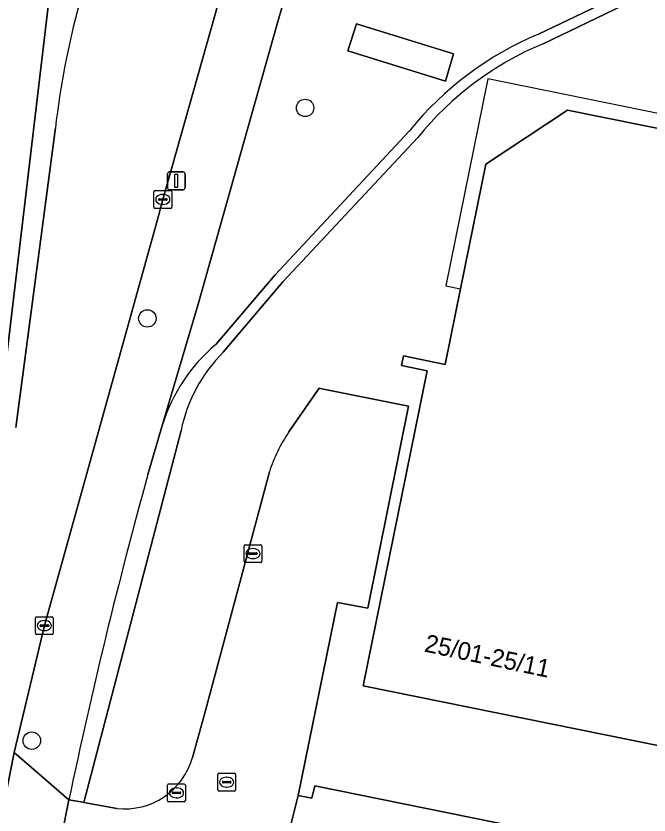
# Model space of a CAD drawing. Extents: x 157692 to 159674, y 381452 to 383291.
# Drawn here: x 158509.71 to 158545.26, y 382034.2 to 382079.09 of the extents above; entities that cross this region are included whole.
import ezdxf

# ---------------------------------------------------------------- set-up
doc = ezdxf.new("R2010")
doc.units = 0
for name, color, linetype in [('IMGEO_Boom', 7, 'Continuous'), ('IMGEO_Erf', 7, 'Continuous'), ('IMGEO_Groenvoorziening', 7, 'Continuous'), ('IMGEO_Haag', 7, 'Continuous'), ('IMGEO_Kolk', 7, 'Continuous'), ('IMGEO_Lichtmast', 7, 'Continuous'), ('IMGEO_Pand', 7, 'Continuous'), ('IMGEO_Pand_nummerreeks', 7, 'Continuous'), ('IMGEO_Pand_overbouw', 7, 'Continuous'), ('IMGEO_Rijbaan_lokaal_gesloten', 7, 'Continuous'), ('IMGEO_Rijbaan_lokaal_open', 7, 'Continuous'), ('IMGEO_Rioolput', 7, 'Continuous'), ('IMGEO_Verkeerseiland_groen', 7, 'Continuous'), ('IMGEO_Voetpad_gesloten', 7, 'Continuous'), ('IMGEO_Voetpad_open', 7, 'Continuous')]:
    doc.layers.add(name, color=color, linetype=linetype)

msp = doc.modelspace()

# ---------------------------------------------------------------- linework, layer by layer
at = {"layer": 'IMGEO_Boom'}
for centre in [(158525.946, 382073.928), (158517.084, 382062.098), (158510.594, 382038.377)]:
    msp.add_circle(centre, 0.489, dxfattribs=at)
at = {"layer": 'IMGEO_Erf'}
for points in [[(158549.351, 382081.923), (158544.304, 382079.926), (158539.307, 382077.53)], [(158545.753, 382038.099), (158529.205, 382041.46), (158532.366, 382057.038), (158532.796, 382059.159), (158531.366, 382059.452), (158531.476, 382059.991), (158533.808, 382059.514), (158534.67, 382063.763), (158536.091, 382070.76), (158540.685, 382073.808), (158551.628, 382071.582)], [(158532.278, 382072.266), (158524.702, 382064.158), (158521.35, 382060.207)], [(158525.034, 382055.722), (158526.735, 382058.178), (158526.89, 382058.147), (158531.761, 382057.161), (158529.467, 382045.826), (158527.765, 382046.147), (158525.552, 382035.293), (158526.323, 382035.147), (158526.484, 382035.842), (158558.034, 382029.439), (158559.163, 382029.191)], [(158518.976, 382055.81), (158513.524, 382034.906), (158515.374, 382034.573)], [(158519.613, 382037.428), (158520.266, 382039.789), (158523.937, 382053.475)]]:
    msp.add_lwpolyline(points, dxfattribs=at)
for centre, radius, start, end in [((158546.234, 382060.956), 17.963, 112.681, 140.9779), ((158527.558, 382054.016), 8.767, 135.0777, 168.1919), ((158532.278, 382050.794), 8.761, 145.7735, 162.1826), ((158515.818, 382038.488), 3.94, 263.5322, 344.3889)]:
    msp.add_arc(centre, radius, start, end, dxfattribs=at)
at = {"layer": 'IMGEO_Groenvoorziening'}
for points in [[(158532.785, 382090.725), (158530.685, 382089.566), (158531.088, 382089.437), (158530.655, 382088.082), (158529.462, 382088.463), (158529.505, 382088.595), (158526.701, 382085.7), (158526.634, 382085.603), (158526.156, 382084.918), (158525.864, 382083.985), (158524.781, 382080.019), (158524.718, 382079.809), (158524.35, 382078.573), (158519.936, 382062.893), (158517.941, 382056.136)], [(158539.307, 382077.53), (158544.304, 382079.926), (158549.351, 382081.923), (158553.579, 382082.999), (158557.322, 382083.532), (158561.047, 382084.02), (158565.823, 382083.768), (158570.839, 382083.106), (158574.936, 382082.265), (158656.531, 382065.514), (158658.251, 382065.165), (158658.369, 382065.753), (158656.651, 382066.102), (158575.057, 382082.853), (158570.941, 382083.698), (158565.878, 382084.366), (158561.024, 382084.622), (158557.24, 382084.126), (158553.463, 382083.589), (158549.165, 382082.495), (158544.064, 382080.476), (158539.061, 382078.078)], [(158539.061, 382078.078), (158544.064, 382080.476), (158549.165, 382082.495)], [(158520.926, 382060.631), (158524.254, 382064.558), (158531.812, 382072.644)], [(158531.812, 382072.644), (158524.254, 382064.558), (158520.926, 382060.631)], [(158521.35, 382060.207), (158524.702, 382064.158), (158532.278, 382072.266)], [(158517.941, 382056.136), (158517.115, 382053.336)], [(158512.682, 382035.058), (158513.351, 382034.937), (158513.524, 382034.906), (158518.976, 382055.81)]]:
    msp.add_lwpolyline(points, dxfattribs=at)
msp.add_lwpolyline([(158534.274, 382076.969), (158533.821, 382075.438), (158528.352, 382077.128), (158528.826, 382078.647)], close=True, dxfattribs=at)
for centre, radius, start, end in [((158546.239, 382060.95), 18.572, 112.7386, 140.9734), ((158546.239, 382060.95), 18.572, 112.7386, 140.9734), ((158546.234, 382060.956), 17.963, 112.681, 140.9779), ((158527.111, 382053.285), 9.603, 130.0967, 162.7294), ((158527.111, 382053.285), 9.603, 130.0967, 162.7294), ((158527.558, 382054.016), 8.767, 135.0777, 168.1919), ((158799.672, 381975.13), 293.18, 164.52906, 168.20529)]:
    msp.add_arc(centre, radius, start, end, dxfattribs=at)
at = {"layer": 'IMGEO_Haag'}
for points in [[(158539.307, 382077.53), (158544.304, 382079.926), (158549.351, 382081.923), (158553.579, 382082.999), (158557.322, 382083.532), (158561.047, 382084.02), (158565.823, 382083.768), (158570.839, 382083.106), (158574.936, 382082.265), (158656.531, 382065.514), (158658.251, 382065.165), (158658.369, 382065.753), (158656.651, 382066.102), (158575.057, 382082.853), (158570.941, 382083.698), (158565.878, 382084.366), (158561.024, 382084.622), (158557.24, 382084.126), (158553.463, 382083.589), (158549.165, 382082.495), (158544.064, 382080.476), (158539.061, 382078.078)], [(158531.812, 382072.644), (158524.254, 382064.558), (158520.926, 382060.631)], [(158521.35, 382060.207), (158524.702, 382064.158), (158532.278, 382072.266)], [(158517.941, 382056.136), (158517.115, 382053.336)], [(158512.682, 382035.058), (158513.351, 382034.937), (158513.524, 382034.906), (158518.976, 382055.81)]]:
    msp.add_lwpolyline(points, dxfattribs=at)
for centre, radius, start, end in [((158546.239, 382060.95), 18.572, 112.7386, 140.9734), ((158546.234, 382060.956), 17.963, 112.681, 140.9779), ((158527.111, 382053.285), 9.603, 130.0967, 162.7294), ((158527.558, 382054.016), 8.767, 135.0777, 168.1919), ((158799.672, 381975.13), 293.18, 164.52906, 168.20529)]:
    msp.add_arc(centre, radius, start, end, dxfattribs=at)
at = {"layer": 'IMGEO_Kolk'}
for p, q in [((158517.527, 382069.284), (158518.379, 382069.284)), ((158517.452, 382068.358), (158517.452, 382069.21)), ((158517.94, 382069.064), (158517.965, 382069.064)), ((158518.453, 382069.21), (158518.453, 382068.358)), ((158517.711, 382068.778), (158517.711, 382068.79)), ((158518.149, 382068.741), (158517.751, 382068.741)), ((158517.754, 382068.827), (158518.152, 382068.827)), ((158517.963, 382068.504), (158517.938, 382068.504)), ((158518.195, 382068.79), (158518.195, 382068.778)), ((158518.379, 382068.284), (158517.527, 382068.284)), ((158522.515, 382048.459), (158522.515, 382049.311)), ((158522.59, 382049.385), (158523.442, 382049.385)), ((158523.003, 382049.165), (158523.028, 382049.165)), ((158523.516, 382049.311), (158523.516, 382048.459)), ((158522.774, 382048.879), (158522.774, 382048.891)), ((158523.212, 382048.842), (158522.814, 382048.842)), ((158522.817, 382048.928), (158523.215, 382048.928)), ((158523.258, 382048.891), (158523.258, 382048.879)), ((158523.442, 382048.385), (158522.59, 382048.385)), ((158523.026, 382048.605), (158523.001, 382048.605)), ((158510.799, 382044.415), (158510.799, 382045.267)), ((158510.874, 382045.341), (158511.726, 382045.341)), ((158511.287, 382045.121), (158511.312, 382045.121)), ((158511.8, 382045.267), (158511.8, 382044.415)), ((158511.058, 382044.835), (158511.058, 382044.847)), ((158511.496, 382044.798), (158511.098, 382044.798)), ((158511.101, 382044.884), (158511.499, 382044.884)), ((158511.542, 382044.847), (158511.542, 382044.835)), ((158511.726, 382044.341), (158510.874, 382044.341)), ((158511.31, 382044.561), (158511.285, 382044.561)), ((158518.219, 382035.019), (158518.219, 382035.871)), ((158518.294, 382035.945), (158519.146, 382035.945)), ((158518.707, 382035.725), (158518.732, 382035.725)), ((158519.22, 382035.871), (158519.22, 382035.019)), ((158518.478, 382035.439), (158518.478, 382035.451)), ((158518.916, 382035.402), (158518.518, 382035.402)), ((158518.521, 382035.488), (158518.919, 382035.488)), ((158518.73, 382035.165), (158518.705, 382035.165)), ((158518.962, 382035.451), (158518.962, 382035.439)), ((158519.146, 382034.945), (158518.294, 382034.945))]:
    msp.add_line(p, q, dxfattribs=at)
for points in [[(158517.527, 382069.284), (158518.379, 382069.284)], [(158517.452, 382068.358), (158517.452, 382069.21)], [(158518.453, 382069.21), (158518.453, 382068.358)], [(158518.379, 382068.284), (158517.527, 382068.284)], [(158522.515, 382048.459), (158522.515, 382049.311)], [(158522.59, 382049.385), (158523.442, 382049.385)], [(158523.516, 382049.311), (158523.516, 382048.459)], [(158523.442, 382048.385), (158522.59, 382048.385)], [(158510.799, 382044.415), (158510.799, 382045.267)], [(158510.874, 382045.341), (158511.726, 382045.341)], [(158511.8, 382045.267), (158511.8, 382044.415)], [(158511.726, 382044.341), (158510.874, 382044.341)], [(158518.219, 382035.019), (158518.219, 382035.871)], [(158518.294, 382035.945), (158519.146, 382035.945)], [(158519.22, 382035.871), (158519.22, 382035.019)], [(158519.146, 382034.945), (158518.294, 382034.945)]]:
    msp.add_lwpolyline(points, dxfattribs=at)
for centre, radius, start, end in [((158517.529, 382069.208), 0.0765, 91.552, 178.448), ((158517.529, 382069.208), 0.0765, 91.552, 178.448), ((158518.377, 382069.208), 0.0765, 1.552, 88.448), ((158518.377, 382069.208), 0.0765, 1.552, 88.448), ((158517.751, 382068.787), 0.0403, 85.8775, 175.7526), ((158517.748, 382068.777), 0.0366, 178.938, 274.7102), ((158518.152, 382068.784), 0.043, 264.8664, 352.4533), ((158518.156, 382068.789), 0.0386, 1.7309, 96.639), ((158517.529, 382068.36), 0.0765, 181.552, 268.448), ((158517.529, 382068.36), 0.0765, 181.552, 268.448), ((158518.377, 382068.36), 0.0765, 271.552, 358.448), ((158518.377, 382068.36), 0.0765, 271.552, 358.448), ((158522.592, 382049.309), 0.0765, 91.552, 178.448), ((158522.592, 382049.309), 0.0765, 91.552, 178.448), ((158523.44, 382049.309), 0.0765, 1.552, 88.448), ((158523.44, 382049.309), 0.0765, 1.552, 88.448), ((158522.814, 382048.888), 0.0403, 85.8775, 175.7526), ((158522.811, 382048.878), 0.0366, 178.938, 274.7102), ((158523.215, 382048.885), 0.043, 264.8664, 352.4533), ((158523.219, 382048.89), 0.0386, 1.7309, 96.639), ((158522.592, 382048.461), 0.0765, 181.552, 268.448), ((158522.592, 382048.461), 0.0765, 181.552, 268.448), ((158523.44, 382048.461), 0.0765, 271.552, 358.448), ((158523.44, 382048.461), 0.0765, 271.552, 358.448), ((158510.876, 382045.265), 0.0765, 91.552, 178.448), ((158510.876, 382045.265), 0.0765, 91.552, 178.448), ((158511.724, 382045.265), 0.0765, 1.552, 88.448), ((158511.724, 382045.265), 0.0765, 1.552, 88.448), ((158511.098, 382044.844), 0.0403, 85.8775, 175.7526), ((158511.095, 382044.834), 0.0366, 178.938, 274.7102), ((158511.499, 382044.841), 0.043, 264.8664, 352.4533), ((158511.503, 382044.846), 0.0386, 1.7309, 96.639), ((158510.876, 382044.417), 0.0765, 181.552, 268.448), ((158510.876, 382044.417), 0.0765, 181.552, 268.448), ((158511.724, 382044.417), 0.0765, 271.552, 358.448), ((158511.724, 382044.417), 0.0765, 271.552, 358.448), ((158518.296, 382035.869), 0.0765, 91.552, 178.448), ((158518.296, 382035.869), 0.0765, 91.552, 178.448), ((158519.144, 382035.869), 0.0765, 1.552, 88.448), ((158519.144, 382035.869), 0.0765, 1.552, 88.448), ((158518.518, 382035.448), 0.0403, 85.8775, 175.7526), ((158518.515, 382035.438), 0.0366, 178.938, 274.7102), ((158518.919, 382035.445), 0.043, 264.8664, 352.4533), ((158518.923, 382035.45), 0.0386, 1.7309, 96.639), ((158518.296, 382035.021), 0.0765, 181.552, 268.448), ((158518.296, 382035.021), 0.0765, 181.552, 268.448), ((158519.144, 382035.021), 0.0765, 271.552, 358.448), ((158519.144, 382035.021), 0.0765, 271.552, 358.448)]:
    msp.add_arc(centre, radius, start, end, dxfattribs=at)
for centre, major_axis, ratio, start_param, end_param in [((158517.939, 382068.784), (-0.387, 0.002), 0.722429, 4.712389, 7.853982), ((158517.964, 382068.784), (-0.39, 0.002), 0.717154, 1.570796, 4.712389), ((158523.002, 382048.885), (-0.387, 0.002), 0.722429, 4.712389, 7.853982), ((158523.027, 382048.885), (-0.39, 0.002), 0.717154, 1.570796, 4.712389), ((158511.286, 382044.841), (-0.387, 0.002), 0.722429, 4.712389, 7.853982), ((158511.311, 382044.841), (-0.39, 0.002), 0.717154, 1.570796, 4.712389), ((158518.706, 382035.445), (-0.387, 0.002), 0.722429, 4.712389, 7.853982), ((158518.731, 382035.445), (-0.39, 0.002), 0.717154, 1.570796, 4.712389)]:
    msp.add_ellipse(centre, major_axis=major_axis, ratio=ratio, start_param=start_param, end_param=end_param, dxfattribs=at)
at = {"layer": 'IMGEO_Lichtmast'}
for p, q in [((158518.214, 382069.429), (158518.214, 382070.229)), ((158518.214, 382070.229), (158518.214, 382069.429)), ((158518.314, 382070.329), (158519.104, 382070.329)), ((158519.104, 382070.329), (158518.314, 382070.329)), ((158519.204, 382070.229), (158519.204, 382069.429)), ((158519.204, 382069.429), (158519.204, 382070.229)), ((158519.104, 382069.329), (158518.314, 382069.329)), ((158518.314, 382069.329), (158519.104, 382069.329))]:
    msp.add_line(p, q, dxfattribs=at)
msp.add_lwpolyline([(158518.634, 382070.204), (158518.784, 382070.204), (158518.784, 382069.454), (158518.634, 382069.454), (158518.634, 382070.204)], dxfattribs=at)
for centre, start, end in [((158518.314, 382070.229), 90, 180), ((158518.314, 382070.229), 90, 180), ((158519.104, 382070.229), 0, 90), ((158519.104, 382070.229), 360, 90), ((158518.314, 382069.429), 180, 270), ((158518.314, 382069.429), 180, 270), ((158519.104, 382069.429), 270, 0), ((158519.104, 382069.429), 270, 0)]:
    msp.add_arc(centre, 0.1, start, end, dxfattribs=at)
at = {"layer": 'IMGEO_Pand'}
msp.add_lwpolyline([(158551.628, 382071.582), (158540.685, 382073.808), (158536.091, 382070.76), (158534.67, 382063.763), (158533.808, 382059.514), (158531.476, 382059.991), (158531.366, 382059.452), (158532.796, 382059.159), (158532.366, 382057.038), (158529.205, 382041.46), (158545.753, 382038.099)], dxfattribs=at)
at = {"layer": 'IMGEO_Pand_overbouw'}
msp.add_lwpolyline([(158550.462, 382061.663), (158552.592, 382072.218), (158536.201, 382075.556), (158533.857, 382063.927), (158534.67, 382063.763), (158536.091, 382070.76), (158540.685, 382073.808), (158551.628, 382071.582), (158549.651, 382061.827)], close=True, dxfattribs=at)
at = {"layer": 'IMGEO_Rijbaan_lokaal_gesloten'}
for points in [[(158508.697, 382056.078), (158513.126, 382093.234), (158513.642, 382096.469), (158517.751, 382095.712), (158516.827, 382092.435), (158513.246, 382079.747)], [(158505.431, 382068.251), (158502.977, 382050.581), (158502.374, 382046.61), (158501.804, 382043.842), (158500, 382035.157), (158498.813, 382029.208), (158507.645, 382027.843), (158509.607, 382037.718), (158511.299, 382044.841), (158517.633, 382067.591), (158517.953, 382068.784), (158520.916, 382079.242), (158521.192, 382080.355)], [(158511.918, 382072.801), (158509.705, 382055.975)]]:
    msp.add_lwpolyline(points, dxfattribs=at)
msp.add_arc((158559.598, 382067.285), 47.998, 164.9516, 173.4009, dxfattribs=at)
at = {"layer": 'IMGEO_Rijbaan_lokaal_open'}
for points in [[(158520.515, 382023.224), (158520.771, 382023.159), (158522.762, 382022.762), (158523.422, 382026.011), (158524.275, 382030.209), (158525.552, 382035.293), (158527.765, 382046.147), (158529.467, 382045.826), (158531.761, 382057.161), (158526.89, 382058.147), (158526.735, 382058.178), (158525.034, 382055.722)], [(158523.937, 382053.475), (158520.266, 382039.789), (158519.613, 382037.428)], [(158559.163, 382029.191), (158558.034, 382029.439), (158526.484, 382035.842), (158526.323, 382035.147), (158525.552, 382035.293), (158524.275, 382030.209), (158524.803, 382030.122)], [(158515.374, 382034.573), (158513.524, 382034.906), (158513.351, 382034.937), (158512.682, 382035.058), (158511.487, 382029.103), (158512.544, 382028.902)]]:
    msp.add_lwpolyline(points, dxfattribs=at)
for centre, radius, start, end in [((158532.278, 382050.794), 8.761, 145.7735, 162.1826), ((158515.818, 382038.488), 3.94, 263.5322, 344.3889)]:
    msp.add_arc(centre, radius, start, end, dxfattribs=at)
at = {"layer": 'IMGEO_Rioolput'}
for p, q in [((158521.115, 382036.546), (158521.967, 382036.546)), ((158521.04, 382035.62), (158521.04, 382036.472)), ((158521.342, 382036.089), (158521.74, 382036.089)), ((158521.528, 382036.326), (158521.553, 382036.326)), ((158522.041, 382036.472), (158522.041, 382035.62)), ((158521.299, 382036.04), (158521.299, 382036.052)), ((158521.737, 382036.003), (158521.339, 382036.003)), ((158521.551, 382035.766), (158521.526, 382035.766)), ((158521.783, 382036.052), (158521.783, 382036.04)), ((158521.967, 382035.546), (158521.115, 382035.546))]:
    msp.add_line(p, q, dxfattribs=at)
for points in [[(158521.115, 382036.546), (158521.967, 382036.546)], [(158521.04, 382035.62), (158521.04, 382036.472)], [(158522.041, 382036.472), (158522.041, 382035.62)], [(158521.967, 382035.546), (158521.115, 382035.546)]]:
    msp.add_lwpolyline(points, dxfattribs=at)
for centre, radius, start, end in [((158521.117, 382036.47), 0.0765, 91.552, 178.448), ((158521.117, 382036.47), 0.0765, 91.552, 178.448), ((158521.965, 382036.47), 0.0765, 1.552, 88.448), ((158521.965, 382036.47), 0.0765, 1.552, 88.448), ((158521.339, 382036.049), 0.0403, 85.8775, 175.7526), ((158521.744, 382036.051), 0.0386, 1.7309, 96.639), ((158521.117, 382035.622), 0.0765, 181.552, 268.448), ((158521.117, 382035.622), 0.0765, 181.552, 268.448), ((158521.336, 382036.039), 0.0366, 178.938, 274.7102), ((158521.74, 382036.046), 0.043, 264.8664, 352.4533), ((158521.965, 382035.622), 0.0765, 271.552, 358.448), ((158521.965, 382035.622), 0.0765, 271.552, 358.448)]:
    msp.add_arc(centre, radius, start, end, dxfattribs=at)
for centre, major_axis, ratio, start_param, end_param in [((158521.527, 382036.046), (-0.387, 0.002), 0.722429, 4.712389, 7.853982), ((158521.552, 382036.046), (-0.39, 0.002), 0.717154, 1.570796, 4.712389)]:
    msp.add_ellipse(centre, major_axis=major_axis, ratio=ratio, start_param=start_param, end_param=end_param, dxfattribs=at)
at = {"layer": 'IMGEO_Verkeerseiland_groen'}
for points in [[(158513.126, 382093.234), (158508.697, 382056.078)], [(158509.705, 382055.975), (158511.918, 382072.801)]]:
    msp.add_lwpolyline(points, dxfattribs=at)
msp.add_arc((158559.598, 382067.285), 47.998, 164.9516, 173.4009, dxfattribs=at)
at = {"layer": 'IMGEO_Voetpad_gesloten'}
msp.add_lwpolyline([(158534.274, 382076.969), (158528.826, 382078.647), (158528.352, 382077.128), (158533.821, 382075.438)], close=True, dxfattribs=at)
at = {"layer": 'IMGEO_Voetpad_open'}
for points in [[(158519.936, 382062.893), (158524.35, 382078.573), (158524.718, 382079.809), (158524.781, 382080.019), (158521.192, 382080.355), (158520.916, 382079.242), (158517.953, 382068.784), (158517.633, 382067.591), (158511.299, 382044.841), (158509.607, 382037.718), (158512.682, 382035.058)], [(158517.115, 382053.336), (158517.941, 382056.136), (158519.936, 382062.893)]]:
    msp.add_lwpolyline(points, dxfattribs=at)
msp.add_lwpolyline([(158507.645, 382027.843), (158511.487, 382029.103), (158512.682, 382035.058), (158509.607, 382037.718)], close=True, dxfattribs=at)
msp.add_arc((158799.672, 381975.13), 293.18, 164.52906, 168.20529, dxfattribs=at)

# ---------------------------------------------------------------- texts
at = {"layer": 'IMGEO_Pand_nummerreeks'}
msp.add_text('25/01-25/11', height=1, rotation=348.0185, dxfattribs=at).set_placement((158532.596, 382043.392))

doc.saveas('drawing.dxf')
